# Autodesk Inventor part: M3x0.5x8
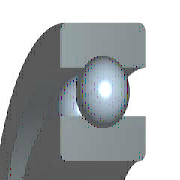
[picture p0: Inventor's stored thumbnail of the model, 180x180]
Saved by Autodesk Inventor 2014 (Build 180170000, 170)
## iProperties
Created: 2009-02
Part Number: M3x0.5x8
Material: 강, 연강
Description: 깊은 그루브 볼 베어링
Document SubType Name: Modeling
Standard: KS B 2023
Designer: KYOUNG IL JANG
Standards Organization: KS
Language: ko-KR
Size Designation: 6201 - 12 x 32 x 10
Categories: <MemberInstance><Categories><Category DisplayName="샤프트 부품" InternalName="7f7aeb1f-a693-4053-b835-cee3144e0d98" Mnemonic="SHFT"><Category DisplayName="베어링" Inter
Density: 7.86 g/cm^3
Mass: 32.7519 g
Surface Area: 42.5728 cm^2
Volume: 4.16691 cm^3
Vendor: CBT Solutions
Appearance: 강철
Company: 한국ATC센터
IsCustomPart: 1
Author: KYOUNG IL JANG
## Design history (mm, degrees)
sketch "스케치" dims "d0" = 5.2 (= -0.26 x WD + 0.26 x BD)
  geometry: L1 (2.4, 11)-(7.6, 11); L2 (5, 11)-(5, 8.4); L3 (5, 11)-(5, 13.6); L4 (3.068, 9.26)-(0, 9.26); L5 (0, 6)-(10, 6); L6 (3.068, 12.74)-(0, 12.74); L7 (0, 16)-(10, 16); L8 (10, 6)-(10, 9.26); L9 (6.932, 9.26)-(10, 9.26); L10 (6.932, 12.74)-(10, 12.74); L11 (10, 16)-(10, 12.74); L12 (-1.4, 0)-(8.4, 0) reference; L13 (0, -0.3)-(0, 5.3) reference
  constraints: 22 end point, 4 point on line, 2 collinear, 2 perpendicular, 2 symmetric about line, 1 midpoint, 1 parallel, 14 other
  dimensions: "d9" = 12 diameter of L5 L12 (= WD); "d11" = 32 diameter of L7 L12 (= BD); "d12" = 10 distance between parallel lines of L8 L13 (= KB); "d13" = 18.52 diameter of L9 L12 (= 0.326 x BD + 0.674 x WD)
revolve "본체" stored, may be unused: angle "d6" = 90 deg
revolve "볼" stored, may be unused: angle "d7" = 90 deg
pattern_circular "IDS_ARRAYBALL[SIMPL:T]" dims angle "d3" = 360 deg
body "Solid1"
fillet "모깎기1" dims "d1" = 0.6 (= KRS)
other parameters: "WD" = 12 [user parameter; used in 5 equation terms], "BD" = 32 [user parameter; used in 5 equation terms], "KB" = 10 [user parameter; used in 1 equation term], "KRS" = 0.6 [user parameter; used in 1 equation term], "d4" = 0, "d5" = 0, "d8" = 0, "d14" = 0, "d15" = 0, "BBA" = 0 [user parameter], "BC0" = 3100000 [user parameter], "BC" = 6890000 [user parameter], "BR" = 16 (= 0.5 x BD) [user parameter], "WR" = 6 (= 0.5 x WD) [user parameter]
